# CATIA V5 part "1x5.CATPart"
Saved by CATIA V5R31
Part number: 1x5
Definition: 5m Beam 4210686/32316
Nomenclature: 5m Beam 4210686/32316
Source: Unknown
Bounding box of the stored display mesh (mm): x -0.1 to 7.101, y -3.6 to 35.6, z 0 to 8
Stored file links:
  C:\Users\super\Desktop\LEGO\TFG-2621\TFG_02621_anejos\1x5.CATPart
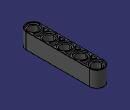
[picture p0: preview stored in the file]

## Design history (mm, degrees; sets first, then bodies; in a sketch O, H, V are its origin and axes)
AxisSystem1: origin (0, 0, 0), X (1, 0, 0), Y (0, 1, 0), Z (0, 0, 1)
Body1 "Body1" (main body)
  Solid1: solid without history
